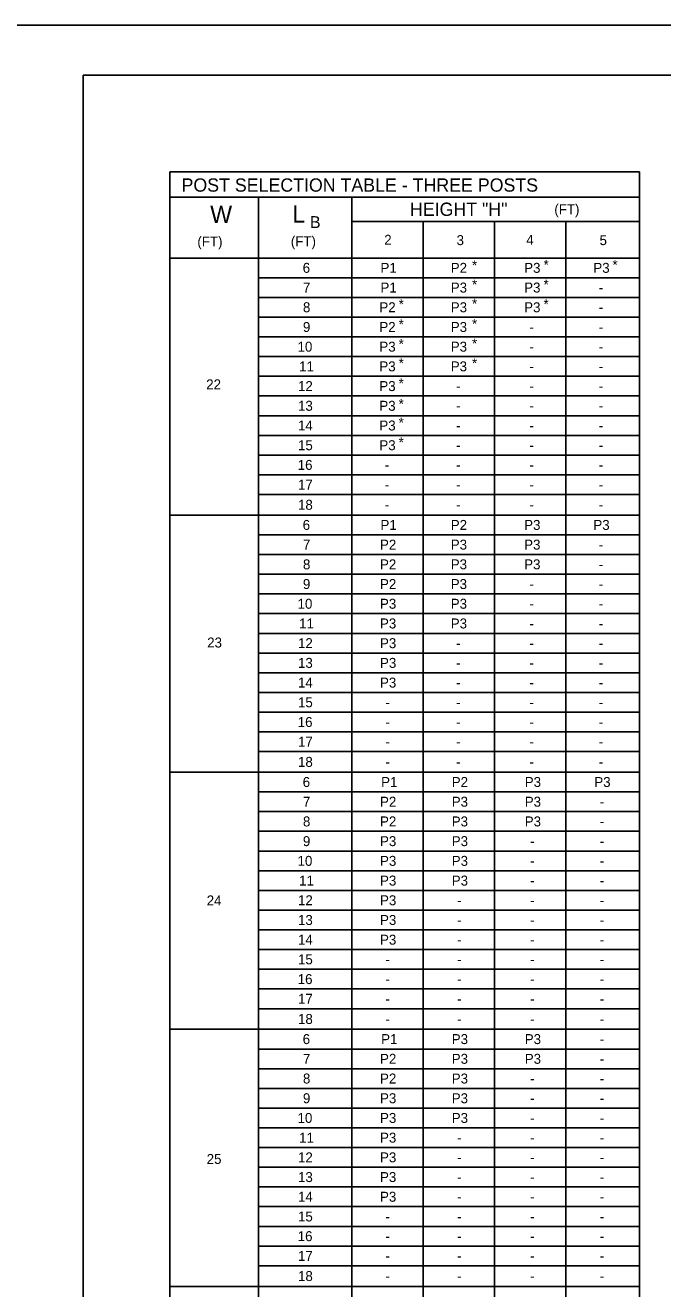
# Model space of a CAD drawing. Extents: x -2340 to 628, y -879 to 309.
# Drawn here: x -253.8 to -61.9, y -71.4 to 309.4 of the extents above; entities that cross this region are included whole.
import ezdxf

# ---------------------------------------------------------------- set-up
doc = ezdxf.new("R2010")
doc.units = 0
for name, color, linetype in [('Level 1', 7, 'Continuous'), ('Level 2', 7, 'Continuous'), ('PLT-BNDY', 7, 'Continuous')]:
    doc.layers.add(name, color=color, linetype=linetype)

msp = doc.modelspace()

# ---------------------------------------------------------------- linework, layer by layer
at = {"layer": 'Level 1'}
for p, q in [((-236.39, 294.44), (549.61, 294.44)), ((-236.39, 294.44), (-236.39, -269.56)), ((-210.36, -148.17), (-210.36, 265.3)), ((-210.36, 265.3), (-68.88, 265.3)), ((-68.88, -148.17), (-68.88, 265.3)), ((-210.36, 257.63), (-68.88, 257.63)), ((-183.56, -148.17), (-183.56, 257.63)), ((-155.55, -148.17), (-155.55, 257.63)), ((-134.05, -148.17), (-134.05, 250.28)), ((-112.55, -148.17), (-112.55, 250.28)), ((-91.05, -148.17), (-91.05, 250.28)), ((-210.36, 239.28), (-68.88, 239.28)), ((-210.36, -70.68), (-68.88, -70.68))]:
    msp.add_line(p, q, dxfattribs=at)
at = {"layer": 'Level 2'}
for p, q in [((-155.55, 250.28), (-68.88, 250.28)), ((-183.56, 233.34), (-68.88, 233.34)), ((-183.56, 227.4), (-68.88, 227.4)), ((-183.56, 221.46), (-68.88, 221.46)), ((-183.56, 215.52), (-68.88, 215.52)), ((-183.56, 209.58), (-68.88, 209.58)), ((-183.56, 203.64), (-68.88, 203.64)), ((-183.56, 197.7), (-68.88, 197.7)), ((-183.56, 191.76), (-68.88, 191.76)), ((-183.56, 185.82), (-68.88, 185.82)), ((-183.56, 179.88), (-68.88, 179.88)), ((-183.56, 173.94), (-68.88, 173.94)), ((-183.56, 168), (-68.88, 168)), ((-210.36, 161.79), (-68.88, 161.79)), ((-183.56, 155.85), (-68.88, 155.85)), ((-183.56, 149.91), (-68.88, 149.91)), ((-183.56, 143.97), (-68.88, 143.97)), ((-183.56, 138.03), (-68.88, 138.03)), ((-183.56, 132.09), (-68.88, 132.09)), ((-183.56, 126.15), (-68.88, 126.15)), ((-183.56, 120.21), (-68.88, 120.21)), ((-183.56, 114.27), (-68.88, 114.27)), ((-183.56, 108.33), (-68.88, 108.33)), ((-183.56, 102.39), (-68.88, 102.39)), ((-183.56, 96.45), (-68.88, 96.45)), ((-183.56, 90.51), (-68.88, 90.51)), ((-210.36, 84.3), (-68.88, 84.3)), ((-183.56, 78.36), (-68.88, 78.36)), ((-183.56, 72.42), (-68.88, 72.42)), ((-108.57, 72.42), (-72.93, 72.42)), ((-183.56, 66.48), (-68.88, 66.48)), ((-108.57, 66.48), (-72.93, 66.48)), ((-183.56, 60.54), (-68.88, 60.54)), ((-108.57, 60.54), (-72.93, 60.54)), ((-183.56, 54.6), (-68.88, 54.6)), ((-108.57, 54.6), (-72.93, 54.6)), ((-183.56, 48.66), (-68.88, 48.66)), ((-183.56, 42.72), (-68.88, 42.72)), ((-183.56, 36.78), (-68.88, 36.78)), ((-108.57, 36.78), (-72.93, 36.78)), ((-183.56, 30.84), (-68.88, 30.84)), ((-183.56, 24.9), (-68.88, 24.9)), ((-183.56, 18.96), (-68.88, 18.96)), ((-108.57, 18.96), (-72.93, 18.96)), ((-183.56, 13.02), (-68.88, 13.02)), ((-210.36, 6.81), (-68.88, 6.81)), ((-183.56, 0.87), (-68.88, 0.87)), ((-108.57, 0.87), (-72.93, 0.87)), ((-183.56, -5.07), (-68.88, -5.07)), ((-183.56, -11.01), (-68.88, -11.01)), ((-108.57, -11.01), (-72.93, -11.01)), ((-183.56, -16.95), (-68.88, -16.95)), ((-183.56, -22.89), (-68.88, -22.89)), ((-183.56, -28.83), (-68.88, -28.83)), ((-183.56, -34.77), (-68.88, -34.77)), ((-183.56, -40.71), (-68.88, -40.71)), ((-183.56, -46.65), (-68.88, -46.65)), ((-183.56, -52.59), (-68.88, -52.59)), ((-108.57, -52.59), (-72.93, -52.59)), ((-183.56, -58.53), (-68.88, -58.53)), ((-183.56, -64.47), (-68.88, -64.47)), ((-108.57, -64.47), (-72.93, -64.47))]:
    msp.add_line(p, q, dxfattribs=at)
at = {"layer": 'PLT-BNDY'}
msp.add_lwpolyline([(-276.39, 309.44), (564.61, 309.44), (564.61, -284.56), (-276.39, -284.56)], close=True, dxfattribs=at)

# ---------------------------------------------------------------- texts
at = {"layer": 'Level 1'}
for s, height, p in [('POST SELECTION TABLE - THREE POSTS', 4.003, (-206.79, 259.28)), ('HEIGHT "H"', 4.003, (-138, 251.98)), ('(FT)', 3, (-94.52, 252.49)), ('W', 5.25, (-198.17, 249.85)), ('L', 5.16, (-173.42, 249.96)), ('B', 3.6, (-168.13, 248.3)), ('(FT)', 3, (-202.02, 242.76)), ('(FT)', 3, (-173.88, 242.82))]:
    msp.add_text(s, height=height, dxfattribs=at).set_placement(p)
for s, p in [('2', (-145.74, 243.27)), ('3', (-123.96, 243.17)), ('4', (-102.97, 243.27)), ('5', (-80.9, 243.17))]:
    msp.add_text(s, height=3, rotation=360, dxfattribs=at).set_placement(p)
at = {"layer": 'Level 2'}
for s, p in [('6', (-170.3, 234.82)), ('P1', (-146.87, 234.82)), ('P2', (-125.71, 234.82)), ('*', (-119.31, 235.6)), ('P3', (-103.6, 234.82)), ('*', (-97.76, 235.73)), ('P3', (-82.76, 234.82)), ('*', (-77.01, 235.73)), ('*', (-119.31, 229.8)), ('*', (-97.76, 229.8)), ('7', (-170.22, 228.88)), ('P1', (-146.87, 228.88)), ('P3', (-125.71, 228.88)), ('P3', (-103.6, 228.88)), ('-', (-81.14, 228.88)), ('8', (-170.22, 222.94)), ('P2', (-147.21, 222.94)), ('*', (-141.41, 223.87)), ('P3', (-125.71, 222.94)), ('*', (-119.31, 224)), ('P3', (-103.6, 222.94)), ('*', (-97.76, 223.87)), ('*', (-119.31, 217.94)), ('-', (-81.14, 222.94)), ('9', (-170.23, 217)), ('P2', (-147.21, 217)), ('*', (-141.41, 217.8)), ('P3', (-125.71, 217)), ('-', (-101.98, 217)), ('-', (-81.14, 217)), ('10', (-171.85, 211.06)), ('P3', (-147.21, 211.06)), ('*', (-141.41, 211.87)), ('P3', (-125.71, 211.06)), ('*', (-119.31, 212.01)), ('-', (-101.98, 211.06)), ('-', (-81.14, 211.06)), ('11', (-171.38, 205.12)), ('P3', (-147.21, 205.12)), ('*', (-141.41, 206.08)), ('P3', (-125.71, 205.12)), ('*', (-119.31, 206.08)), ('-', (-101.98, 205.12)), ('-', (-81.14, 205.12)), ('22', (-199.36, 199.7)), ('12', (-171.72, 199.18)), ('P3', (-147.21, 199.18)), ('*', (-141.41, 200.01)), ('-', (-124.09, 199.18)), ('-', (-101.98, 199.18)), ('-', (-81.14, 199.18)), ('13', (-171.72, 193.24)), ('P3', (-147.21, 193.24)), ('*', (-141.41, 193.81)), ('-', (-124.09, 193.24)), ('-', (-101.98, 193.24)), ('-', (-81.14, 193.24)), ('*', (-141.41, 188.15)), ('14', (-171.72, 187.3)), ('P3', (-147.21, 187.3)), ('-', (-124.09, 187.3)), ('-', (-101.98, 187.3)), ('-', (-81.14, 187.3)), ('15', (-171.72, 181.36)), ('P3', (-147.21, 181.36)), ('*', (-141.41, 182.22)), ('-', (-124.09, 181.36)), ('-', (-101.98, 181.36)), ('-', (-81.14, 181.36)), ('16', (-171.8, 175.42)), ('-', (-145.6, 175.42)), ('-', (-124.09, 175.42)), ('-', (-101.98, 175.42)), ('-', (-81.14, 175.42)), ('17', (-171.72, 169.48)), ('-', (-145.6, 169.48)), ('-', (-124.09, 169.48)), ('-', (-101.98, 169.48)), ('-', (-81.14, 169.48)), ('18', (-171.72, 163.4)), ('-', (-145.6, 163.4)), ('-', (-124.09, 163.4)), ('-', (-101.98, 163.4)), ('-', (-81.14, 163.4)), ('6', (-170.3, 157.33)), ('P1', (-146.87, 157.33)), ('P2', (-125.71, 157.33)), ('P3', (-103.6, 157.33)), ('P3', (-82.76, 157.33)), ('7', (-170.22, 151.39)), ('P2', (-147.02, 151.39)), ('P3', (-125.71, 151.39)), ('P3', (-103.6, 151.39)), ('-', (-81.15, 151.39)), ('8', (-170.22, 145.45)), ('P2', (-147.02, 145.45)), ('P3', (-125.71, 145.45)), ('P3', (-103.6, 145.45)), ('-', (-81.14, 145.45)), ('9', (-170.23, 139.51)), ('P2', (-147.02, 139.51)), ('P3', (-125.71, 139.51)), ('-', (-101.99, 139.51)), ('-', (-81.14, 139.51)), ('10', (-171.85, 133.57)), ('P3', (-147.02, 133.57)), ('P3', (-125.71, 133.57)), ('-', (-101.99, 133.57)), ('-', (-81.14, 133.57)), ('11', (-171.38, 127.63)), ('P3', (-147.02, 127.63)), ('P3', (-125.71, 127.63)), ('-', (-101.99, 127.63)), ('-', (-81.14, 127.63)), ('23', (-199.07, 121.89)), ('12', (-171.72, 121.69)), ('P3', (-147.02, 121.69)), ('-', (-124.09, 121.69)), ('-', (-101.99, 121.69)), ('-', (-81.14, 121.69)), ('13', (-171.72, 115.75)), ('P3', (-147.02, 115.75)), ('-', (-124.09, 115.75)), ('-', (-101.99, 115.75)), ('-', (-81.14, 115.75)), ('14', (-171.72, 109.81)), ('P3', (-147.02, 109.81)), ('-', (-124.09, 109.81)), ('-', (-101.99, 109.81)), ('-', (-81.14, 109.81)), ('15', (-171.72, 103.87)), ('-', (-145.4, 103.87)), ('-', (-124.09, 103.87)), ('-', (-101.99, 103.87)), ('-', (-81.14, 103.87)), ('16', (-171.8, 97.93)), ('-', (-145.4, 97.93)), ('-', (-124.09, 97.93)), ('-', (-101.99, 97.93)), ('-', (-81.14, 97.93)), ('17', (-171.72, 91.99)), ('-', (-145.4, 91.99)), ('-', (-124.09, 91.99)), ('-', (-101.99, 91.99)), ('-', (-81.14, 91.99)), ('18', (-171.72, 85.91)), ('-', (-145.4, 85.91)), ('-', (-124.09, 85.91)), ('-', (-101.99, 85.91)), ('-', (-81.14, 85.91)), ('6', (-170.3, 79.84)), ('P1', (-146.67, 79.84)), ('P2', (-125.41, 79.84)), ('P3', (-103.42, 79.84)), ('P3', (-82.47, 79.84)), ('7', (-170.22, 73.9)), ('P2', (-147.01, 73.9)), ('P3', (-125.41, 73.9)), ('P3', (-103.42, 73.9)), ('-', (-80.85, 73.9)), ('8', (-170.22, 67.96)), ('P2', (-147.01, 67.96)), ('P3', (-125.41, 67.96)), ('P3', (-103.42, 67.96)), ('-', (-80.85, 67.96)), ('9', (-170.23, 62.02)), ('P3', (-147.01, 62.02)), ('P3', (-125.41, 62.02)), ('-', (-101.81, 62.02)), ('-', (-80.85, 62.02)), ('10', (-171.85, 56.08)), ('P3', (-147.01, 56.08)), ('P3', (-125.41, 56.08)), ('-', (-101.81, 56.08)), ('-', (-80.85, 56.08)), ('11', (-171.38, 50.14)), ('P3', (-147.01, 50.14)), ('P3', (-125.41, 50.14)), ('-', (-101.81, 50.14)), ('-', (-80.85, 50.14)), ('24', (-199.21, 44.14)), ('12', (-171.72, 44.2)), ('P3', (-147.01, 44.2)), ('-', (-123.79, 44.2)), ('-', (-101.81, 44.2)), ('-', (-80.85, 44.2)), ('13', (-171.72, 38.26)), ('P3', (-147.01, 38.26)), ('-', (-123.79, 38.26)), ('-', (-101.81, 38.26)), ('-', (-80.85, 38.26)), ('14', (-171.72, 32.32)), ('P3', (-147.01, 32.32)), ('-', (-123.79, 32.32)), ('-', (-101.81, 32.32)), ('-', (-80.85, 32.32)), ('15', (-171.72, 26.38)), ('-', (-145.39, 26.38)), ('-', (-123.79, 26.38)), ('-', (-101.81, 26.38)), ('-', (-80.85, 26.38)), ('16', (-171.8, 20.44)), ('-', (-145.39, 20.44)), ('-', (-123.79, 20.44)), ('-', (-101.81, 20.44)), ('-', (-80.85, 20.44)), ('17', (-171.72, 14.5)), ('-', (-145.39, 14.5)), ('-', (-123.79, 14.5)), ('-', (-101.81, 14.5)), ('-', (-80.85, 14.5)), ('18', (-171.72, 8.42)), ('-', (-145.39, 8.42)), ('-', (-123.79, 8.42)), ('-', (-101.81, 8.42)), ('-', (-80.85, 8.42)), ('6', (-170.3, 2.35)), ('P1', (-146.67, 2.35)), ('P3', (-125.41, 2.35)), ('P3', (-103.42, 2.35)), ('-', (-80.85, 2.35)), ('7', (-170.22, -3.59)), ('P2', (-147.01, -3.59)), ('P3', (-125.41, -3.59)), ('P3', (-103.42, -3.59)), ('-', (-80.85, -3.59)), ('8', (-170.22, -9.53)), ('P2', (-147.01, -9.53)), ('P3', (-125.41, -9.53)), ('-', (-101.81, -9.53)), ('-', (-80.85, -9.53)), ('9', (-170.23, -15.47)), ('P3', (-147.01, -15.47)), ('P3', (-125.41, -15.47)), ('-', (-101.81, -15.47)), ('-', (-80.85, -15.47)), ('10', (-171.85, -21.41)), ('P3', (-147.01, -21.41)), ('P3', (-125.41, -21.41)), ('-', (-101.81, -21.41)), ('-', (-80.85, -21.41)), ('11', (-171.38, -27.35)), ('P3', (-147.01, -27.35)), ('-', (-123.79, -27.35)), ('-', (-101.81, -27.35)), ('-', (-80.85, -27.35)), ('12', (-171.72, -33.29)), ('P3', (-147.01, -33.29)), ('25', (-199.21, -33.78)), ('-', (-123.79, -33.29)), ('-', (-101.81, -33.29)), ('-', (-80.85, -33.29)), ('13', (-171.72, -39.23)), ('P3', (-147.01, -39.23)), ('-', (-123.79, -39.23)), ('-', (-101.81, -39.23)), ('-', (-80.85, -39.23)), ('14', (-171.72, -45.17)), ('P3', (-147.01, -45.17)), ('-', (-123.79, -45.17)), ('-', (-101.81, -45.17)), ('-', (-80.85, -45.17)), ('15', (-171.72, -51.11)), ('-', (-145.39, -51.11)), ('-', (-123.79, -51.11)), ('-', (-101.81, -51.11)), ('-', (-80.85, -51.11)), ('16', (-171.8, -57.05)), ('-', (-145.39, -57.05)), ('-', (-123.79, -57.05)), ('-', (-101.81, -57.05)), ('-', (-80.85, -57.05)), ('17', (-171.72, -62.99)), ('-', (-145.39, -62.99)), ('-', (-123.79, -62.99)), ('-', (-101.81, -62.99)), ('-', (-80.85, -62.99)), ('18', (-171.72, -69.07)), ('-', (-145.39, -69.07)), ('-', (-123.79, -69.07)), ('-', (-101.81, -69.07)), ('-', (-80.85, -69.07))]:
    msp.add_text(s, height=3, dxfattribs=at).set_placement(p)

doc.saveas('drawing.dxf')
